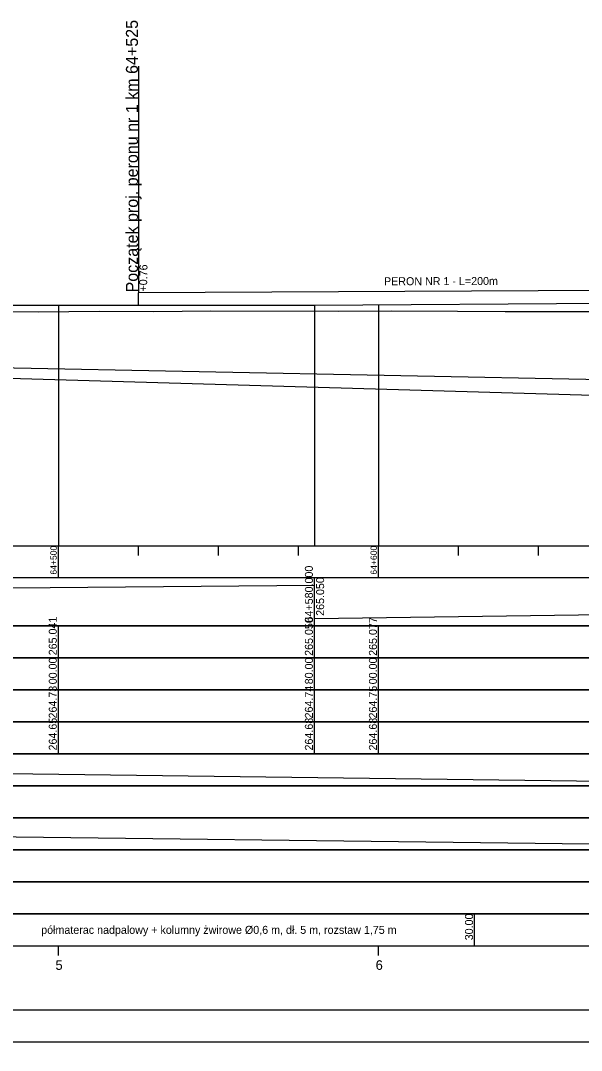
# Model space of a CAD drawing. Extents: x 6531046 to 6533341, y 5514966 to 5518007.
# Drawn here: x 6532184.2 to 6532359.4, y 5517685.4 to 5518007.2 of the extents above; entities that cross this region are included whole.
import ezdxf

# ---------------------------------------------------------------- set-up
doc = ezdxf.new("R2010")
doc.units = 0
for name, color, linetype in [('IR_default', 7, 'Continuous'), ('TOR_PROF-rowy otwarte', 7, 'Continuous'), ('TOR_PROF-tabelka-geometria T1', 7, 'Continuous'), ('TOR_PROF-tabelka-kilometracja', 7, 'Continuous'), ('TOR_PROF-tabelka-odleglosci T1', 7, 'Continuous'), ('TOR_PROF-tabelka-pochylenia proj T1', 7, 'Continuous'), ('TOR_PROF-tabelka-rodzaj rowu T1', 7, 'Continuous'), ('TOR_PROF-tabelka-rowyT1', 7, 'Continuous'), ('TOR_PROF-tabelka-rzedne proj T1', 7, 'Continuous'), ('TOR_PROF-tabelka-teren istniejacy T1', 7, 'Continuous'), ('TOR_PROF-tabelka-warstwa ochronna T1', 7, 'Continuous'), ('TOR_PROF-tor projektowany', 7, 'Continuous'), ('TOR_PROF-uklad odniesienia', 7, 'Continuous'), ('TOR_PROF-warstwa ochronna', 7, 'Continuous'), ('TOR_PROF-wzocnienia podtorza', 7, 'Continuous'), ('TOR_W-warstwa dodatkowa 1', 7, 'Continuous')]:
    doc.layers.add(name, color=color, linetype=linetype)

msp = doc.modelspace()

# ---------------------------------------------------------------- linework, layer by layer
at = {"layer": 'IR_default'}
msp.add_lwpolyline([(6532171.65, 5517916.44), (6532189.86, 5517916.28), (6532208.8, 5517916.47), (6532225.77, 5517916.33), (6532243.67, 5517916.5), (6532283.66, 5517916.47), (6532300.08, 5517916.51), (6532320.72, 5517916.43), (6532335.56, 5517916.33), (6532353.1, 5517916.35), (6532368.44, 5517916.35)], dxfattribs=at)
at = {"layer": 'TOR_PROF-rowy otwarte'}
for q in [(6532396.02, 5517889.26), (6532366.02, 5517895.1)]:
    msp.add_line((6531816.02, 5517906.1), q, dxfattribs=at)
at = {"layer": 'TOR_PROF-tabelka-geometria T1'}
for points in [[(6531096.02, 5517698.1), (6531963.82, 5517698.1), (6531963.82, 5517700.76), (6531985.07, 5517700.76), (6531985.07, 5517698.1), (6532138.26, 5517698.1), (6532138.26, 5517695.43), (6532159.51, 5517695.43), (6532159.51, 5517698.1), (6532589.81, 5517698.1), (6532589.81, 5517700.76), (6532627.31, 5517700.76), (6532627.31, 5517698.1), (6532842.64, 5517698.1), (6532842.64, 5517695.43), (6532880.14, 5517695.43), (6532880.14, 5517698.1), (6533096.02, 5517698.1)], [(6531096.02, 5517698.1), (6533096.02, 5517698.1)], [(6531096.02, 5517688.1), (6531963.82, 5517688.1), (6531963.82, 5517690.76), (6531985.07, 5517690.76), (6531985.07, 5517688.1), (6532138.26, 5517688.1), (6532138.26, 5517685.43), (6532159.51, 5517685.43), (6532159.51, 5517688.1), (6532589.81, 5517688.1), (6532589.81, 5517690.76), (6532627.31, 5517690.76), (6532627.31, 5517688.1), (6532842.64, 5517688.1), (6532842.64, 5517685.43), (6532880.14, 5517685.43), (6532880.14, 5517688.1), (6533096.02, 5517688.1)], [(6531096.02, 5517688.1), (6533096.02, 5517688.1)]]:
    msp.add_lwpolyline(points, dxfattribs=at)
at = {"layer": 'TOR_PROF-tabelka-kilometracja'}
for points in [[(6532196.02, 5517715.1), (6532196.02, 5517718.1)], [(6532296.02, 5517715.1), (6532296.02, 5517718.1)]]:
    msp.add_lwpolyline(points, dxfattribs=at)
at = {"layer": 'TOR_PROF-tabelka-odleglosci T1'}
msp.add_lwpolyline([(6531096.02, 5517798.1), (6533096.02, 5517798.1), (6533096.02, 5517808.1), (6531096.02, 5517808.1)], close=True, dxfattribs=at)
for points in [[(6532196.02, 5517798.1), (6532196.02, 5517808.1)], [(6532276.02, 5517798.1), (6532276.02, 5517808.1)], [(6532296.02, 5517798.1), (6532296.02, 5517808.1)]]:
    msp.add_lwpolyline(points, dxfattribs=at)
at = {"layer": 'TOR_PROF-tabelka-pochylenia proj T1'}
msp.add_lwpolyline([(6531096.02, 5517818.1), (6533096.02, 5517818.1), (6533096.02, 5517833.1), (6531096.02, 5517833.1)], close=True, dxfattribs=at)
for points in [[(6532276.02, 5517818.1), (6532276.02, 5517833.1)], [(6531096.02, 5517820.35), (6532276.02, 5517830.85)], [(6532276.02, 5517820.35), (6533026.02, 5517830.85)]]:
    msp.add_lwpolyline(points, dxfattribs=at)
at = {"layer": 'TOR_PROF-tabelka-rodzaj rowu T1'}
for points in [[(6531096.02, 5517758.1), (6533096.02, 5517758.1), (6533096.02, 5517768.1), (6531096.02, 5517768.1)], [(6531096.02, 5517738.1), (6533096.02, 5517738.1), (6533096.02, 5517748.1), (6531096.02, 5517748.1)]]:
    msp.add_lwpolyline(points, close=True, dxfattribs=at)
at = {"layer": 'TOR_PROF-tabelka-rowyT1'}
for points in [[(6531096.02, 5517768.1), (6533096.02, 5517768.1), (6533096.02, 5517778.1), (6531096.02, 5517778.1)], [(6531096.02, 5517748.1), (6533096.02, 5517748.1), (6533096.02, 5517758.1), (6531096.02, 5517758.1)]]:
    msp.add_lwpolyline(points, close=True, dxfattribs=at)
for points in [[(6531816.02, 5517776.6), (6532366.02, 5517769.6)], [(6531816.02, 5517756.6), (6532396.02, 5517749.6)]]:
    msp.add_lwpolyline(points, dxfattribs=at)
at = {"layer": 'TOR_PROF-tabelka-rzedne proj T1'}
msp.add_lwpolyline([(6531096.02, 5517808.1), (6533096.02, 5517808.1), (6533096.02, 5517818.1), (6531096.02, 5517818.1)], close=True, dxfattribs=at)
for points in [[(6532196.02, 5517808.1), (6532196.02, 5517818.1)], [(6532276.02, 5517808.1), (6532276.02, 5517818.1)], [(6532296.02, 5517808.1), (6532296.02, 5517818.1)]]:
    msp.add_lwpolyline(points, dxfattribs=at)
at = {"layer": 'TOR_PROF-tabelka-teren istniejacy T1'}
for points in [[(6531096.02, 5517788.1), (6533096.02, 5517788.1), (6533096.02, 5517798.1), (6531096.02, 5517798.1)], [(6531096.02, 5517778.1), (6533096.02, 5517778.1), (6533096.02, 5517788.1), (6531096.02, 5517788.1)]]:
    msp.add_lwpolyline(points, close=True, dxfattribs=at)
for points in [[(6532196.02, 5517788.1), (6532196.02, 5517798.1)], [(6532276.02, 5517788.1), (6532276.02, 5517798.1)], [(6532296.02, 5517788.1), (6532296.02, 5517798.1)], [(6532196.02, 5517778.1), (6532196.02, 5517788.1)], [(6532276.02, 5517778.1), (6532276.02, 5517788.1)], [(6532296.02, 5517778.1), (6532296.02, 5517788.1)]]:
    msp.add_lwpolyline(points, dxfattribs=at)
at = {"layer": 'TOR_PROF-tabelka-warstwa ochronna T1'}
msp.add_lwpolyline([(6532276.02, 5517918.35), (6532276.02, 5517848.1), (6532276.02, 5517843.1), (6532276.02, 5517843.1)], dxfattribs=at)
msp.add_lwpolyline([(6531096.02, 5517728.1), (6533096.02, 5517728.1), (6533096.02, 5517738.1), (6531096.02, 5517738.1)], close=True, dxfattribs=at)
at = {"layer": 'TOR_PROF-tor projektowany'}
for p, q in [((6532276.02, 5517918.35), (6533026.02, 5517923.5)), ((6532276.02, 5517918.35), (6533002.82, 5517923.34)), ((6531096.02, 5517917.66), (6532276.02, 5517918.35))]:
    msp.add_line(p, q, dxfattribs=at)
for points in [[(6532196.02, 5517918.3), (6532196.02, 5517848.1), (6532196.02, 5517843.1), (6532196.02, 5517843.1)], [(6532276.02, 5517918.35), (6532276.02, 5517848.1), (6532276.02, 5517843.1), (6532276.02, 5517843.1)], [(6532296.02, 5517918.49), (6532296.02, 5517848.1), (6532296.02, 5517843.1), (6532296.02, 5517843.1)]]:
    msp.add_lwpolyline(points, dxfattribs=at)
at = {"layer": 'TOR_PROF-uklad odniesienia'}
for p, q in [((6531096.02, 5517843.1), (6533096.02, 5517843.1)), ((6532196.02, 5517833.1), (6532196.02, 5517843.1)), ((6532221.02, 5517840.1), (6532221.02, 5517843.1)), ((6532246.02, 5517840.1), (6532246.02, 5517843.1)), ((6532271.02, 5517840.1), (6532271.02, 5517843.1)), ((6532296.02, 5517833.1), (6532296.02, 5517843.1)), ((6532321.02, 5517840.1), (6532321.02, 5517843.1)), ((6532346.02, 5517840.1), (6532346.02, 5517843.1))]:
    msp.add_line(p, q, dxfattribs=at)
at = {"layer": 'TOR_PROF-warstwa ochronna'}
msp.add_lwpolyline([(6532326.02, 5517718.1), (6532326.02, 5517728.1)], dxfattribs=at)
at = {"layer": 'TOR_PROF-wzocnienia podtorza'}
msp.add_lwpolyline([(6531096.02, 5517718.1), (6533096.02, 5517718.1), (6533096.02, 5517728.1), (6531096.02, 5517728.1)], close=True, dxfattribs=at)
at = {"layer": 'TOR_W-warstwa dodatkowa 1'}
for p, q in [((6532221.14, 5517922.12), (6532221.14, 5517993.02)), ((6532421.09, 5517923.14), (6532221.08, 5517922.12)), ((6532221.08, 5517918.32), (6532221.08, 5517922.12))]:
    msp.add_line(p, q, dxfattribs=at)

# ---------------------------------------------------------------- texts
at = {"layer": 'TOR_PROF-tabelka-kilometracja'}
for s, p in [('5', (6532195.12, 5517710.6)), ('6', (6532295.13, 5517710.6))]:
    msp.add_text(s, height=3, dxfattribs=at).set_placement(p)
at = {"layer": 'TOR_PROF-tabelka-odleglosci T1'}
for s, p in [('00.00', (6532195.52, 5517799.84)), ('80.00', (6532275.52, 5517799.84)), ('00.00', (6532295.52, 5517799.84))]:
    msp.add_text(s, height=2.5, rotation=90, dxfattribs=at).set_placement(p)
at = {"layer": 'TOR_PROF-tabelka-pochylenia proj T1'}
for s, p in [('64+580.000', (6532275.52, 5517819.16)), ('265.050', (6532279.02, 5517821.23))]:
    msp.add_text(s, height=2.5, rotation=90, dxfattribs=at).set_placement(p)
at = {"layer": 'TOR_PROF-tabelka-rzedne proj T1'}
for s, p in [('265.041', (6532195.52, 5517808.9)), ('265.050', (6532275.52, 5517808.73)), ('265.077', (6532295.52, 5517808.73))]:
    msp.add_text(s, height=2.5, rotation=90, dxfattribs=at).set_placement(p)
at = {"layer": 'TOR_PROF-tabelka-teren istniejacy T1'}
for s, p in [('264.73', (6532195.52, 5517789.16)), ('264.74', (6532275.52, 5517789.17)), ('264.75', (6532295.52, 5517789.16)), ('264.65', (6532195.52, 5517779.16)), ('264.68', (6532275.52, 5517779.16)), ('264.68', (6532295.52, 5517779.16))]:
    msp.add_text(s, height=2.5, rotation=90, dxfattribs=at).set_placement(p)
at = {"layer": 'TOR_PROF-uklad odniesienia'}
for s, p in [('64+500', (6532195.52, 5517834.12)), ('64+600', (6532295.52, 5517834.12))]:
    msp.add_text(s, height=2, rotation=90, dxfattribs=at).set_placement(p)
at = {"layer": 'TOR_PROF-warstwa ochronna'}
for s, rotation, p in [('30.00', 90, (6532325.52, 5517719.84)), ('półmaterac nadpalowy + kolumny żwirowe Ø0,6 m, dł. 5 m, rozstaw 1,75 m', 360, (6532190.65, 5517721.85))]:
    msp.add_text(s, height=2.5, rotation=rotation, dxfattribs=at).set_placement(p)
at = {"layer": 'TOR_W-warstwa dodatkowa 1'}
for s, height, rotation, p in [('Początek proj. peronu nr 1 km 64+525', 3.75, 90, (6532220.87, 5517922.29)), ('+0.76', 2.5, 89.0973, (6532223.72, 5517922.56)), ('PERON NR 1 - L=200m', 2.5, 0.1533, (6532297.73, 5517924.53))]:
    msp.add_text(s, height=height, rotation=rotation, dxfattribs=at).set_placement(p)

doc.saveas('drawing.dxf')
